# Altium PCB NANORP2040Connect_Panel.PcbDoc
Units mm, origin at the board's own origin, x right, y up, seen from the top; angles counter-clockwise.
Board outline 211 x 180.46 mm, 4 copper layers (TOP, GND, SIG, BOTTOM), stack 1.586 mm thick; 0 components, 48 nets, 10 pads, 0 vias.
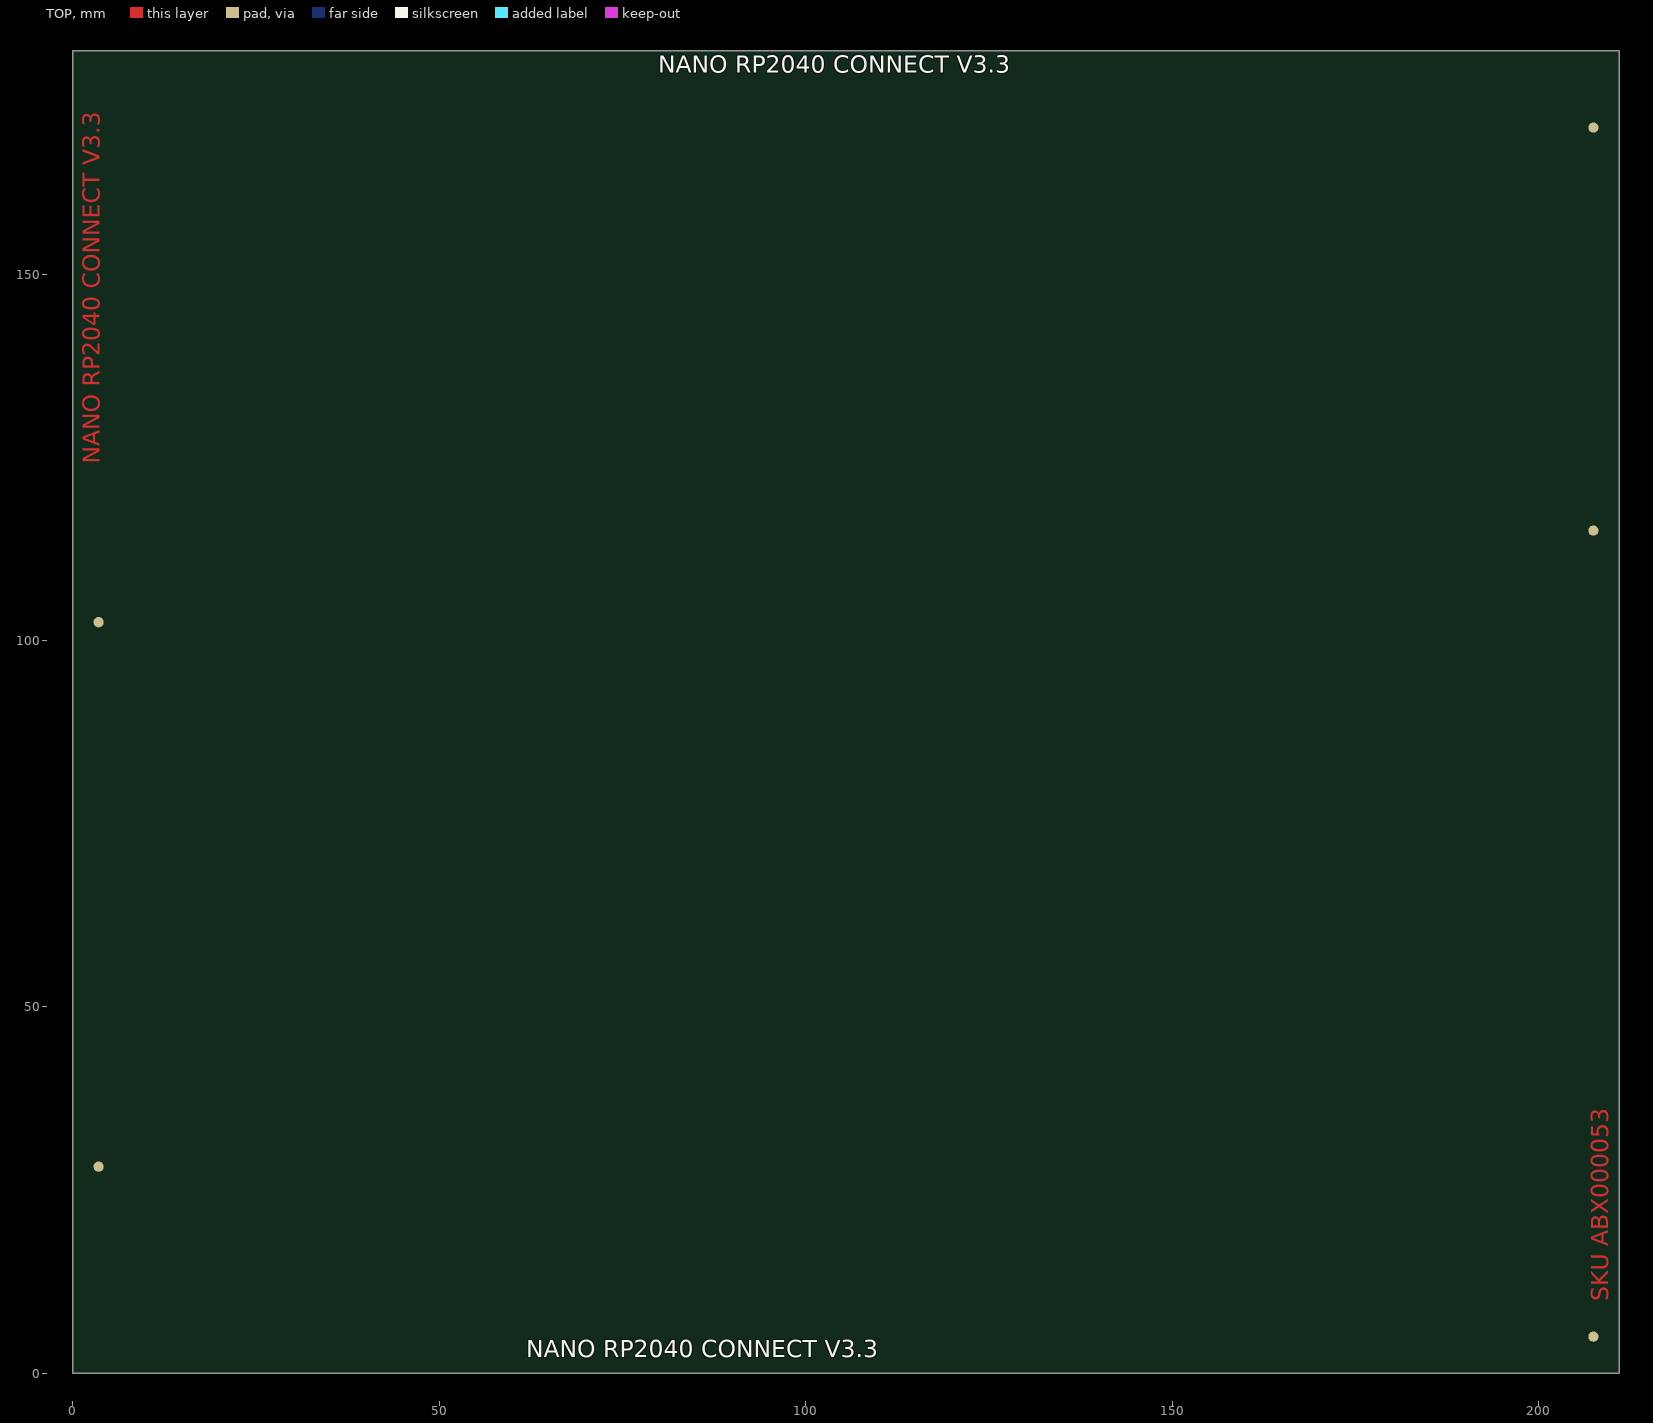
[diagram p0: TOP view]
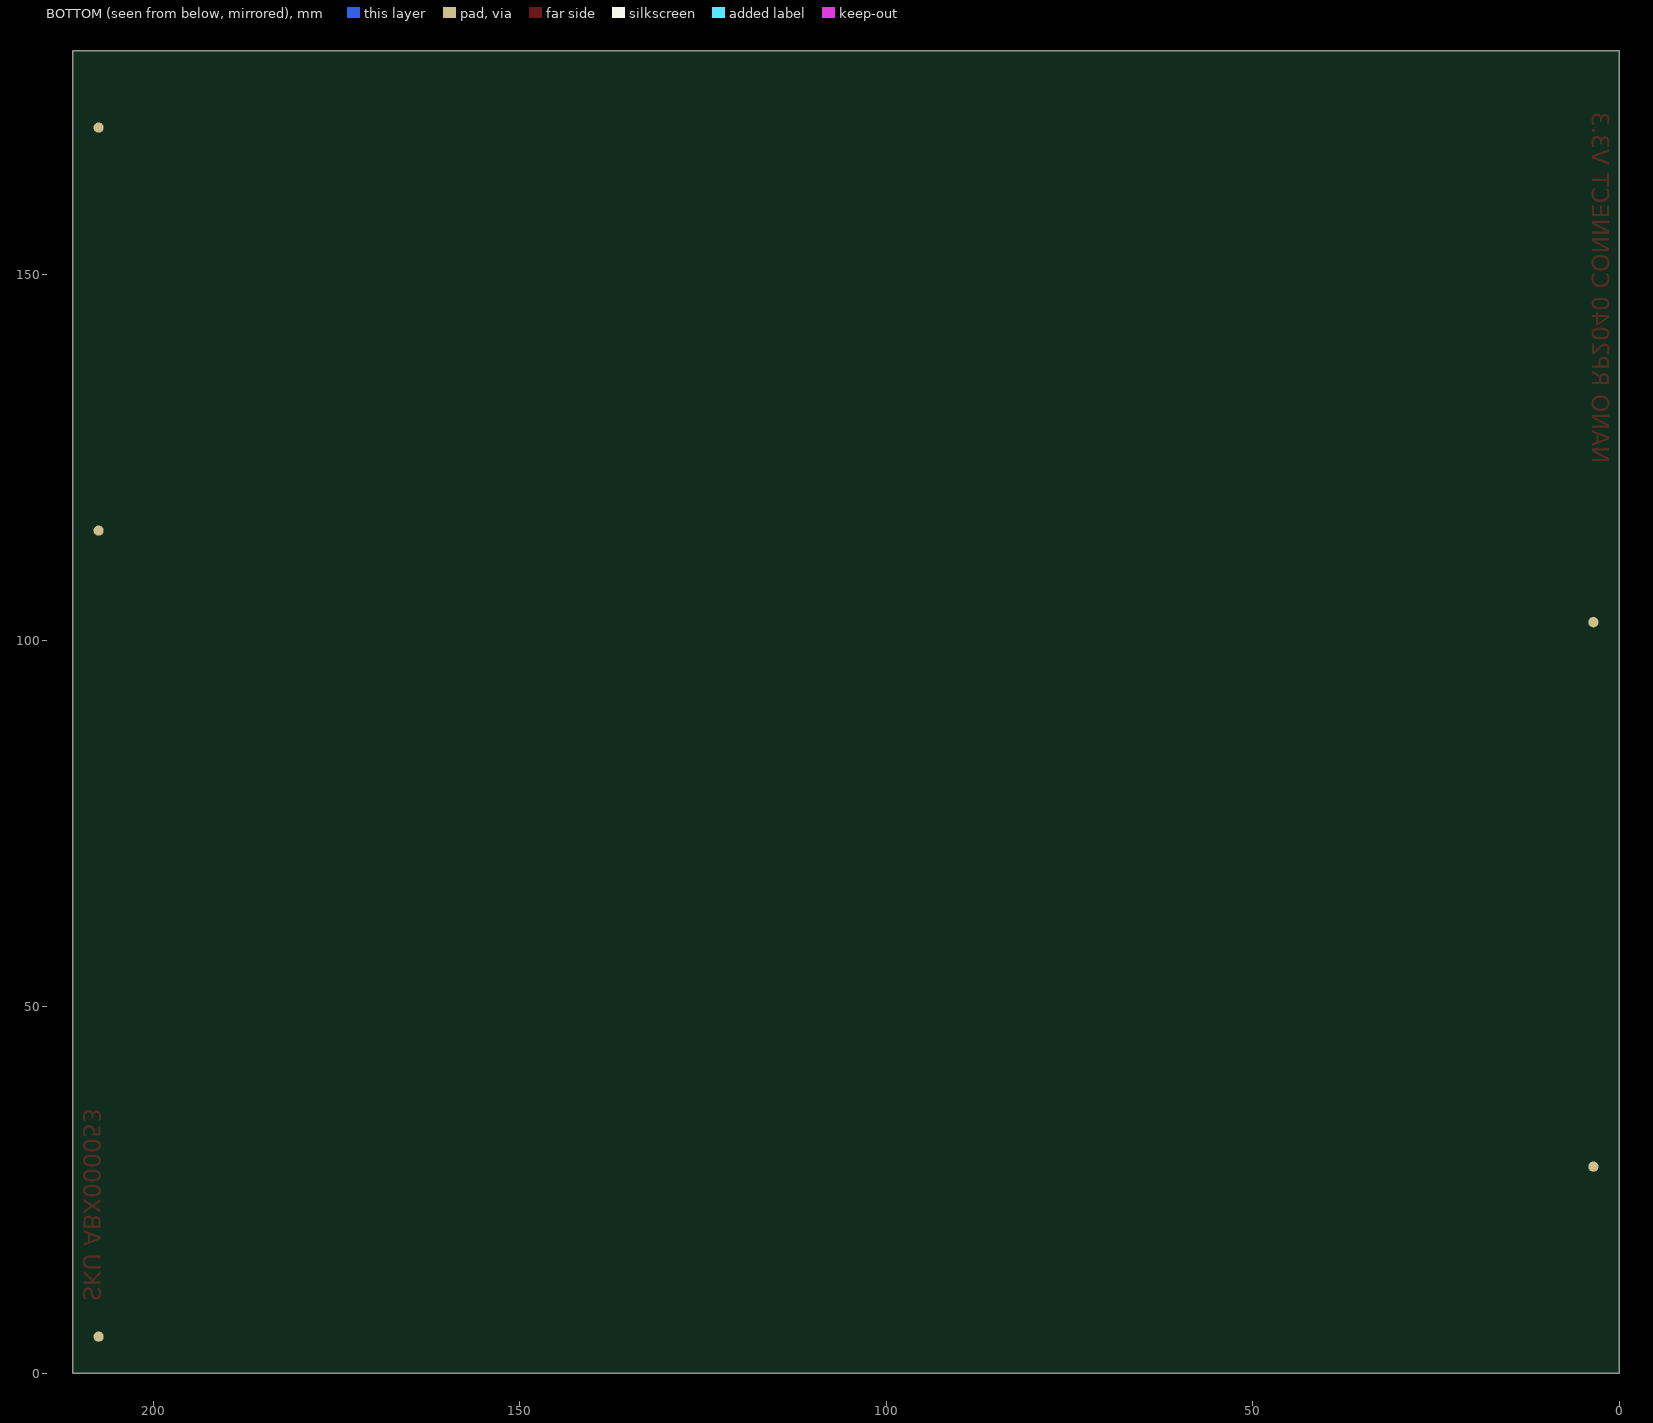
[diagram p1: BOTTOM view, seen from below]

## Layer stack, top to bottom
Top Solder: solder mask 0.0102, Solder Resist, Dk 3.5
TOP: signal copper 0.018
Dielectric 1: prepreg 0.14, PP-014, Dk 4.2
GND: signal copper 0.035
Dielectric2: core 1.2, FR-4, Dk 4.8
SIG: signal copper 0.035
Dielectric3: prepreg 0.14, PP-014, Dk 4.2
BOTTOM: signal copper 0.018
Bottom Solder: solder mask 0.0102, Solder Resist, Dk 3.5

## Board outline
0,0 211,0 211,180.46 0,180.46

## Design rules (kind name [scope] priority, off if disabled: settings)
BoardOutlineClearance [not HasFootprint('PH1-15-UA (CASTELL)') and not OnLayer('TopOverlay') and not OnLayer('BottomOverlay')] p1: gap=0.254 ignorepadtopadclearanceinfootprint=FALSE except(0: Arc-SplitContinuation Track-SplitContinuation SMDPad-SplitContinuation THPad-SplitContinuation Via-SplitContinuation Fill-SplitContinuation Poly-SplitContinuation Region-SplitContinuation Text-SplitContinuation)
BoardOutlineClearance mdCopperDimension [not IsKeepOut and not HasFootprint('PH1-15-UA (CASTELL)') and not OnLayer('TopOverlay') and not OnLayer('BottomOverlay')] p2: gap=0.254 ignorepadtopadclearanceinfootprint=FALSE except(0: Arc-SplitContinuation Track-SplitContinuation SMDPad-SplitContinuation THPad-SplitContinuation Via-SplitContinuation Fill-SplitContinuation Poly-SplitContinuation Region-SplitContinuation Text-SplitContinuation)
Clearance Clearance_for_PolygonClass_Isolate_0 [InPolygonClass('Isolate_0')] p1 off: gap=0 ignorepadtopadclearanceinfootprint=FALSE except(0.254: Poly-Hole)
Clearance Clearance_for_PolygonClass_Isolate_3.94 [InPolygonClass('Isolate_3.94')] p2 off: gap=0 ignorepadtopadclearanceinfootprint=FALSE except(0.1: Arc-Poly Track-Poly SMDPad-Poly THPad-Poly Via-Poly Fill-Poly Poly-Poly Poly-Region Poly-Text; 0.254: Poly-Hole)
Clearance [not Keepout vs not Keepout] p3: gap=0.138 ignorepadtopadclearanceinfootprint=TRUE except(0.127: SMDPad-SMDPad SMDPad-THPad SMDPad-Via THPad-THPad THPad-Via Via-Via)
Clearance "Clearance (Same Net)" [All] p4: gap=0 ignorepadtopadclearanceinfootprint=TRUE
Clearance Clearance_for_NetClass_usb [InNetClass('usb') vs InNetClass('usb')] p5: gap=0.127 ignorepadtopadclearanceinfootprint=FALSE
ComponentClearance ComponentClearance_HEADER [InComponent('JP2') or InComponent('JP3') vs InComponent('JP2') or InComponent('JP3')] p1: gap=0 collisioncheckmode=3 verticalgap=0 showdistances=FALSE
ComponentClearance ComponentClearance_1 [All] p2: gap=0.254 collisioncheckmode=3 verticalgap=0.254 showdistances=FALSE
DiffPairsRouting [All] p1: maxlimit=0.3 minlimit=0.1 mostfreqgap=0.15 toplayer_minwidth=0.2 toplayer_maxwidth=0.254 toplayer_prefwidth=0.2 midlayer1_maxgap=0.2 midlayer1_minwidth=0.2 midlayer1_maxwidth=0.254 midlayer1_prefwidth=0.2 midlayer14_maxgap=0.2 midlayer14_minwidth=0.2 midlayer14_maxwidth=0.254 midlayer14_prefwidth=0.2 bottomlayer_minwidth=0.2 bottomlayer_maxwidth=0.254 bottomlayer_prefwidth=0.2 maxuncoupledlength=12.7
HoleSize HoleSize_For_NetClass_usb [InNetClass('usb')] p1: absolutevalues=TRUE maxlimit=0.19 minlimit=0.19 maxpercent=80.000 minpercent=20.000
HoleSize [All] p2: absolutevalues=TRUE maxlimit=2540 minlimit=0.19 maxpercent=80.000 minpercent=20.000
HoleToHoleClearance mdDrill [All] p1: gap=0.203 allowstackedmicrovias=TRUE
MinimumSolderMaskSliver [All] p1 off: minsoldermaskwidth=0.254
PasteMaskExpansion Expansion_SMDPaste_OFF [InPadClass('All Pads')] p1: expansion=0
PasteMaskExpansion mlMinCreamFrame [All] p2: expansion=0
PolygonConnect PolygonConnect_For_PolygonThermal_ON_Width100000_Gap100000 [InPolygonClass('PolygonThermal_ON_Width100000_Gap100000') vs Not IsVia] p1: connectstyle=Relief reliefconductorwidth=0.254 reliefentries=4 polygonreliefangle="90 Angle" airgapwidth=0.254
PolygonConnect PolygonConnect_For_PolygonThermal_ON_Width98400_Gap100000 [InPolygonClass('PolygonThermal_ON_Width98400_Gap100000') vs Not IsVia] p2: connectstyle=Relief reliefconductorwidth=0.25 reliefentries=4 polygonreliefangle="90 Angle" airgapwidth=0.254
PolygonConnect ThermalVias [IsVia] p3: connectstyle=Relief reliefconductorwidth=0.254 reliefentries=4 polygonreliefangle="90 Angle" airgapwidth=0.1
PolygonConnect [All] p4: connectstyle=Relief reliefconductorwidth=0.254 reliefentries=4 polygonreliefangle="90 Angle" airgapwidth=0.1
RoomDefinition NANOWANV1_0 [InComponentClass('NANOWANV1_0')] p1 off: confinementstyle=ConfineIn formatcopy=TRUE lockcomponents=FALSE outline 0.508,-0.254 61.595,-0.254 61.595,22.225 0.508,22.225
RoutingVias [All] p1: holewidth=0.3 width=0.5 viastyle="Through Hole" minholewidth=0.2 minwidth=0.4 maxholewidth=0.5 maxwidth=0.7
SilkToSolderMaskClearance [IsPad] p1 off: minsilkscreentomaskgap=0.254 clearancetoexposedcopper=TRUE
SolderMaskExpansion Expansion_SMDSolder_OFF [InPadClass('SMDSolder_OFF')] p1: expansion=0 istentingtop=FALSE
SolderMaskExpansion mlMinStopFrame [All] p2: expansion=0.102 istentingtop=FALSE
UnRoutedNet [All] p1: checkbadconnections=TRUE
Width Width_For_NetClass_usb [InNetClass('usb')] p1: maxlimit=0.6 minlimit=0.2 preferedwidth=0.254 minimp=50.000000 maximp=50.000000 favimp=50.000000
Width [All] p2: maxlimit=254 minlimit=0.1 preferedwidth=0.2 minimp=50.000000 maximp=50.000000 favimp=50.000000
22 further rules are at their usual default settings.

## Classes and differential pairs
pad class SMDSolder_OFF: U1-EP
pad class SMDPaste_OFF: U1-EP
differential pair USB: +USB_P -USB_N

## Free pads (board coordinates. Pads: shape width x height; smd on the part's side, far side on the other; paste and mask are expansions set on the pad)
  round 1.4 smd paste-5 mask+1.8: 21(3.5,28.2) 21(3.5,102.5) 21(207.5,5) 21(207.5,115) 21(207.5,170)
  round 1.4 smd far side paste-5 mask+1.8: 21(3.5,28.2) 21(3.5,102.5) 21(207.5,5) 21(207.5,115) 21(207.5,170)

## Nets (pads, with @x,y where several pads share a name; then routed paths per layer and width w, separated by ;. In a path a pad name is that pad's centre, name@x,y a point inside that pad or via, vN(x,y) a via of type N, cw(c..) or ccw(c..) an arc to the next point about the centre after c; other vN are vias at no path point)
+3V3: 
+3V3_HE: 
+5V: 
+VBUCK: 
A0: 
A1: 
A2: 
A3: 
AREF: 
BOOT0: 
D2: 
D3~: 
D5~: 
D6~: 
D9~: 
D10: 
GND: 
MISO: 
MOSI: 
NetC1_2: 
NetC5_2: 
NetC6_2: 
NetDL1_A: 
NetDL2_A: 
NetL1_1: 
NetM1_4: 
NetM1_10: 
NetM1_20: 
NetM1_45: 
NetM1_46: 
NetM1_47: 
NetM1_48: 
NetQ1_G1: 
NetQ1_S1: 
NetR6_2: 
NetR9_2: 
RESETN: 
RX1: 
SCK: 
SCL: 
SDA: 
SWCLK: 
SWDIO: 
TX1: 
USB_N: 
USB_P: 
VIN: 
VUSB: 

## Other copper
TOP:
  text "NANO RP2040 CONNECT V3.3" at 4.5,124.1 h4 r90
  text "SKU ABX000053" at 210.35,9.8 h4 r90

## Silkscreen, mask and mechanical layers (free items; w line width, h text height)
Top Overlay:
  text "NANO RP2040 CONNECT V3.3" at 79.855,176.678 h4
  text "NANO RP2040 CONNECT V3.3" at 61.84,1.357 h4
Top Solder:
  text "NANO RP2040 CONNECT V3.3" at 4.5,124.1 h4 r90
  text "SKU ABX000053" at 210.3,9.8 h4 r90
Route Tool Path:
  text "ROUTE TOOL PATH ON THIS LAYER" at 217.8,144.4 h4
Board:
  the board outline again, w0.1
VSCORING:
  lines w0.2: 8.49,0 8.49,180.46 ; 51.97,0 51.97,180.46 ; 58.67,0 58.67,180.46 ; 102.15,0 102.15,180.46 ; 108.85,0 108.85,180.46 ; 152.33,0 152.33,180.46 ; 159.03,0 159.03,180.46 ; 202.51,0 202.51,180.46
  text "VSCORING LINES ON THIS LAYER" at 217.8,165.4 h4

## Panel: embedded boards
"NANORP2040Connect.PcbDoc" at 8.64,7, 7 rows x 4 columns, spacing 24.78 x 50.18, rotation 0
